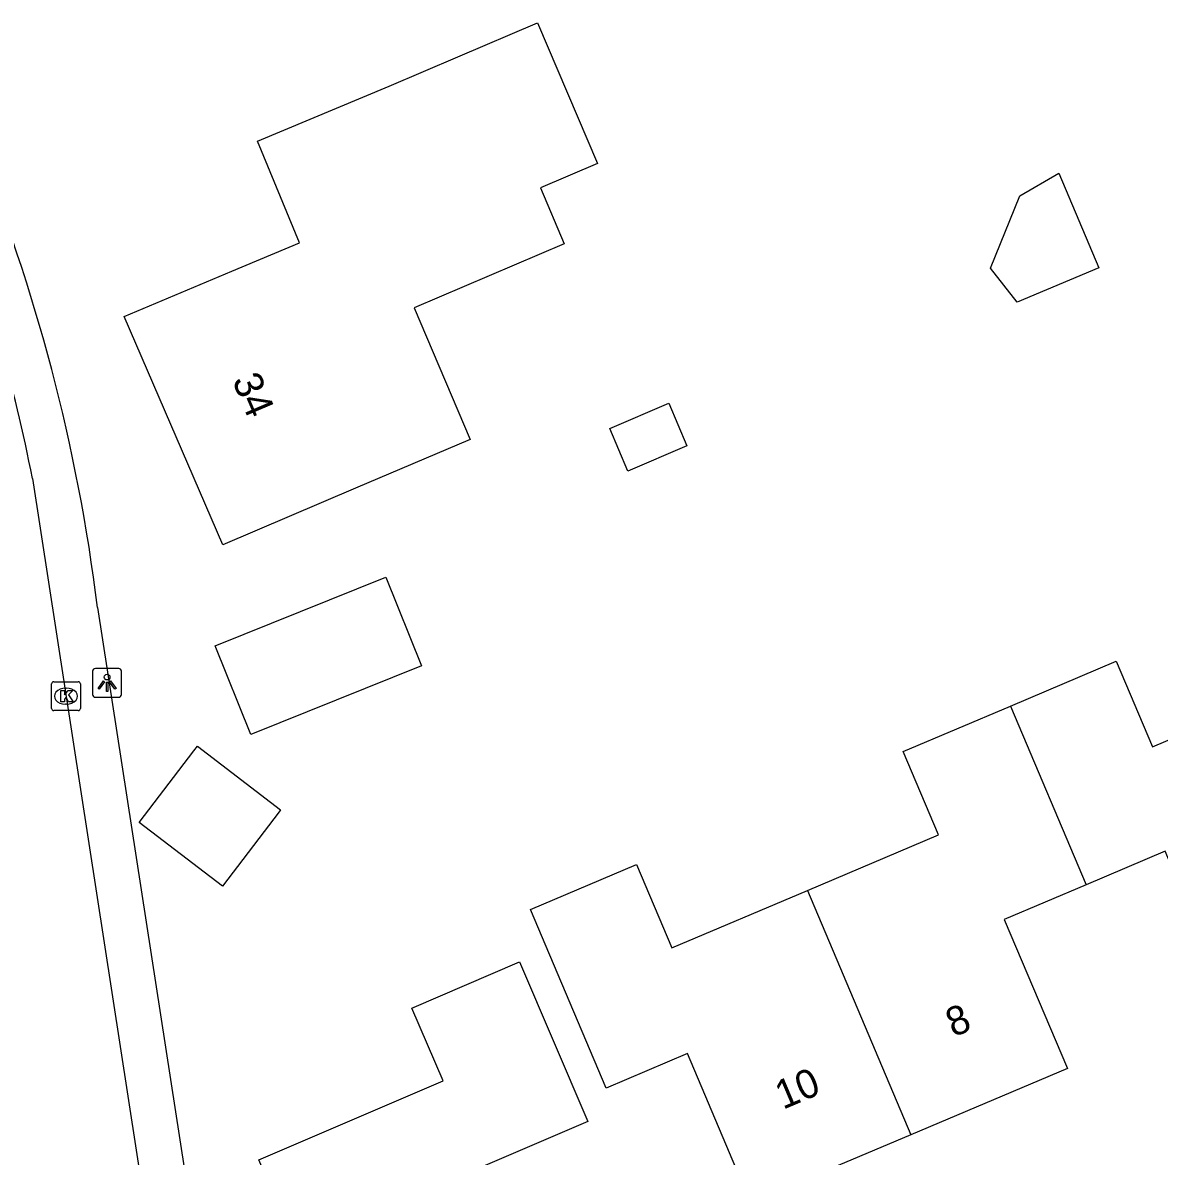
# Model space of a CAD drawing. Extents: x 158474 to 159560, y 388525 to 389605.
# Drawn here: x 158564.62 to 158603.99, y 389039.16 to 389078.41 of the extents above; entities that cross this region are included whole.
import ezdxf

# ---------------------------------------------------------------- set-up
doc = ezdxf.new("R2010")
doc.units = 0
for name, color, linetype in [('IMGEO_Kolk', 7, 'Continuous'), ('IMGEO_Lichtpunt', 7, 'Continuous'), ('IMGEO_Pand', 7, 'Continuous'), ('IMGEO_Pand_nummerreeks', 7, 'Continuous'), ('IMGEO_Rijbaan_lokaal_open', 7, 'Continuous')]:
    doc.layers.add(name, color=color, linetype=linetype)

msp = doc.modelspace()

# ---------------------------------------------------------------- linework, layer by layer
at = {"layer": 'IMGEO_Kolk'}
for p, q in [((158565.688, 389055.594), (158566.54, 389055.594)), ((158565.613, 389054.668), (158565.613, 389055.52)), ((158566.101, 389055.374), (158566.126, 389055.374)), ((158566.614, 389055.52), (158566.614, 389054.668)), ((158566.124, 389054.814), (158566.099, 389054.814)), ((158566.54, 389054.594), (158565.688, 389054.594))]:
    msp.add_line(p, q, dxfattribs=at)
for points in [[(158565.688, 389055.594), (158566.54, 389055.594)], [(158565.613, 389054.668), (158565.613, 389055.52)], [(158565.934, 389055.294), (158566.057, 389055.294), (158566.057, 389055.143), (158566.187, 389055.294), (158566.351, 389055.294), (158566.205, 389055.143), (158566.358, 389054.894), (158566.206, 389054.894), (158566.121, 389055.058), (158566.057, 389054.991), (158566.057, 389054.894), (158565.934, 389054.894), (158565.934, 389055.294)], [(158566.614, 389055.52), (158566.614, 389054.668)], [(158566.54, 389054.594), (158565.688, 389054.594)]]:
    msp.add_lwpolyline(points, dxfattribs=at)
for centre, start, end in [((158565.69, 389055.518), 91.552, 178.448), ((158565.69, 389055.518), 91.552, 178.448), ((158566.538, 389055.518), 1.552, 88.448), ((158566.538, 389055.518), 1.552, 88.448), ((158565.69, 389054.67), 181.552, 268.448), ((158565.69, 389054.67), 181.552, 268.448), ((158566.538, 389054.67), 271.552, 358.448), ((158566.538, 389054.67), 271.552, 358.448)]:
    msp.add_arc(centre, 0.0765, start, end, dxfattribs=at)
for centre, major_axis, ratio, start_param, end_param in [((158566.1, 389055.094), (-0.387, 0.002), 0.722429, 4.712389, 7.853982), ((158566.125, 389055.094), (-0.39, 0.002), 0.717154, 1.570796, 4.712389)]:
    msp.add_ellipse(centre, major_axis=major_axis, ratio=ratio, start_param=start_param, end_param=end_param, dxfattribs=at)
at = {"layer": 'IMGEO_Lichtpunt'}
for p, q in [((158567.94, 389056.052), (158567.132, 389056.052)), ((158567.94, 389056.052), (158567.132, 389056.052)), ((158567.038, 389055.957), (158567.038, 389055.15)), ((158567.038, 389055.957), (158567.038, 389055.15)), ((158568.034, 389055.15), (158568.034, 389055.957)), ((158568.034, 389055.15), (158568.034, 389055.957)), ((158567.132, 389055.056), (158567.94, 389055.056)), ((158567.132, 389055.056), (158567.94, 389055.056))]:
    msp.add_line(p, q, dxfattribs=at)
for points in [[(158567.412, 389055.621), (158567.451, 389055.593), (158567.263, 389055.331), (158567.225, 389055.358), (158567.412, 389055.621)], [(158567.514, 389055.573), (158567.561, 389055.573), (158567.561, 389055.251), (158567.514, 389055.251), (158567.514, 389055.573)], [(158567.624, 389055.593), (158567.662, 389055.62), (158567.849, 389055.358), (158567.81, 389055.33), (158567.624, 389055.593)]]:
    msp.add_lwpolyline(points, dxfattribs=at)
msp.add_circle((158567.537, 389055.755), 0.0994, dxfattribs=at)
for centre, start, end in [((158567.132, 389055.957), 90, 180), ((158567.132, 389055.957), 90, 180), ((158567.94, 389055.957), 0, 90), ((158567.94, 389055.957), 0, 90), ((158567.132, 389055.15), 180, 270), ((158567.132, 389055.15), 180, 270), ((158567.94, 389055.15), 270, 0), ((158567.94, 389055.15), 270, 360)]:
    msp.add_arc(centre, 0.0946, start, end, dxfattribs=at)
at = {"layer": 'IMGEO_Pand'}
for points in [[(158584.528, 389073.537), (158582.55, 389072.693), (158583.376, 389070.756), (158578.174, 389068.538), (158580.116, 389063.986), (158576.149, 389062.294), (158571.549, 389060.332), (158568.126, 389068.238), (158571.863, 389069.815), (158574.209, 389070.796), (158572.751, 389074.307), (158577.311, 389076.221), (158579.689, 389077.235), (158582.449, 389078.412), (158584.528, 389073.537)], [(158600.515, 389073.204), (158601.896, 389069.924), (158599.068, 389068.733), (158598.14, 389069.913), (158599.158, 389072.42), (158600.515, 389073.204)], [(158586.998, 389065.238), (158587.628, 389063.76), (158585.584, 389062.888), (158584.953, 389064.366), (158586.998, 389065.238)], [(158571.283, 389056.835), (158577.19, 389059.217), (158578.429, 389056.144), (158572.522, 389053.762), (158571.283, 389056.835)], [(158598.842, 389054.75), (158602.499, 389056.3), (158603.753, 389053.339), (158608.356, 389055.289)], [(158591.805, 389048.365), (158596.345, 389050.288), (158595.122, 389053.174), (158598.842, 389054.75)], [(158598.842, 389054.75), (158601.463, 389048.565)], [(158573.551, 389051.157), (158573.495, 389051.084), (158571.532, 389048.518), (158568.652, 389050.721), (158570.549, 389053.202), (158570.67, 389053.36), (158573.551, 389051.157)], [(158611.905, 389046.91), (158606.375, 389044.567), (158604.191, 389049.721), (158601.463, 389048.565)], [(158595.387, 389039.909), (158589.835, 389037.557), (158587.649, 389042.716), (158584.833, 389041.522), (158582.882, 389046.126), (158582.213, 389047.706), (158585.879, 389049.26), (158587.102, 389046.373), (158591.805, 389048.365)], [(158601.463, 389048.565), (158598.623, 389047.362), (158600.808, 389042.206), (158595.387, 389039.909)], [(158591.805, 389048.365), (158595.387, 389039.909)], [(158584.194, 389040.362), (158580.476, 389038.767), (158582.751, 389033.466), (158576.363, 389030.724), (158572.797, 389039.033), (158579.179, 389041.772), (158578.097, 389044.293), (158581.821, 389045.891), (158584.194, 389040.362)]]:
    msp.add_lwpolyline(points, dxfattribs=at)
at = {"layer": 'IMGEO_Rijbaan_lokaal_open'}
for points in [[(158564.949, 389062.628), (158569.658, 389032.192), (158571.227, 389022.248)], [(158567.204, 389058.167), (158571.923, 389027.713)]]:
    msp.add_lwpolyline(points, dxfattribs=at)
for centre, radius, start, end in [((158505.178, 389050.505), 62.498, 7.04204, 22.44265), ((158515.205, 389053.126), 50.644, 10.8142, 21.8567)]:
    msp.add_arc(centre, radius, start, end, dxfattribs=at)

# ---------------------------------------------------------------- texts
at = {"layer": 'IMGEO_Pand_nummerreeks'}
for s, rotation, p in [('34', 293.0969, (158571.859, 389066.028)), ('8', 22.9612, (158596.865, 389043.272)), ('10', 22.9612, (158590.954, 389040.767))]:
    msp.add_text(s, height=1, rotation=rotation, dxfattribs=at).set_placement(p)

doc.saveas('drawing.dxf')
